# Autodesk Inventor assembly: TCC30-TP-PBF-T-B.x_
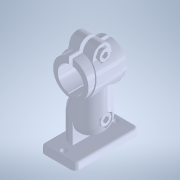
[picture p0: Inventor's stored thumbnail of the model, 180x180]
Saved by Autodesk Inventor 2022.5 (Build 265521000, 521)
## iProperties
Created: 2023-09
Part Number: TCC30-TP-PBF-T-B.x_
Document SubType Name: Assembly
Designer: ImaoCorp
Sending System: SOLIDWORKS 2021-2021301
MC: AMD64
MC_MODEL: Intel64 Family 6 Model 60 Stepping 3, GenuineIntel
OS: Windows_NT
FRU: Parasolid Version 32.1, build 255,  1- 1-2021
FORMAT: text
GUISE: transmit
KEY: TCC30-TP-PBF-T-B
FILE: TCC30-TP-PBF-T-B.x_t
DATE: Fri Sep 15 15:37:55 2023
Author: ImaoCorp
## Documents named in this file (7)
- X:\14_SW2022-Inv2022\00_全2023-1023新製品(TCC)まで\t\tcc30-tp-pbf-t-b\TCC30-TP-PBF-T-B.iam
- X:\14_SW2022-Inv2022\00_全2023-1023新製品(TCC)まで\t\tcc30-tp-pbf-t-b\TCC30-TP-PBF-T-B_01.ipt
- X:\14_SW2022-Inv2022\00_全2023-1023新製品(TCC)まで\t\tcc30-tp-pbf-t-b\TCC30-TP-PBF-T-B_02.ipt
- X:\14_SW2022-Inv2022\00_全2023-1023新製品(TCC)まで\t\tcc30-tp-pbf-t-b\TCC30-TP-PBF-T-B_03.ipt
- X:\14_SW2022-Inv2022\00_全2023-1023新製品(TCC)まで\t\tcc30-tp-pbf-t-b\TCC30-TP-PBF-T-B_04.ipt
- X:\14_SW2022-Inv2022\00_全2023-1023新製品(TCC)まで\t\tcc30-tp-pbf-t-b\TCC30-TP-PBF-T-B_05.ipt
- X:\14_SW2022-Inv2022\00_全2023-1023新製品(TCC)まで\t\tcc30-tp-pbf-t-b\TCC30-TP-PBF-T-B_06.ipt
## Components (6 placed, 6 different names)
1. TCC30-TP-PBF-T-B_01
2. TCC30-TP-PBF-T-B_02
3. TCC30-TP-PBF-T-B_03
4. TCC30-TP-PBF-T-B_04
5. TCC30-TP-PBF-T-B_05
6. TCC30-TP-PBF-T-B_06
